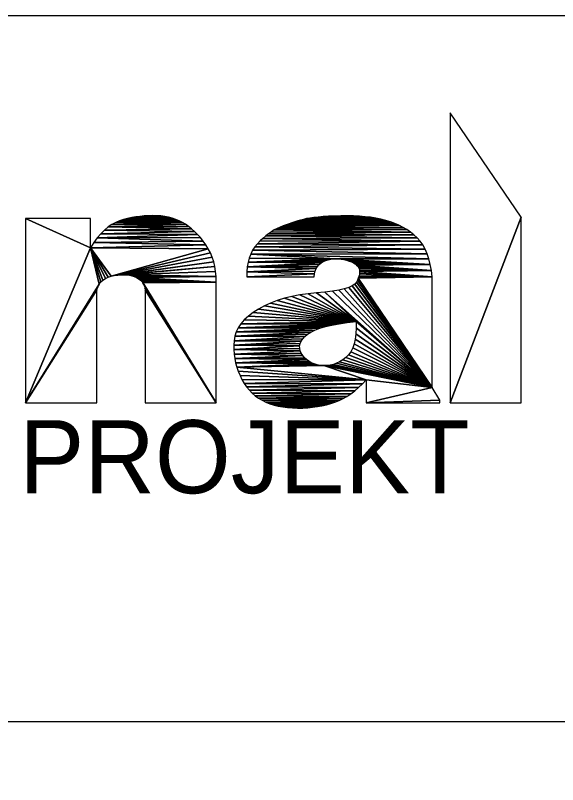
# Model space of a CAD drawing. Extents: x 1400 to 3500, y -1100 to 385.
# Drawn here: x 2698.5 to 2783.8, y -909.9 to -788.9 of the extents above; entities that cross this region are included whole.
import ezdxf

# ---------------------------------------------------------------- set-up
doc = ezdxf.new("R2010")
doc.units = 0
doc.layers.add('Vrstva 1', color=7, linetype='Continuous')

msp = doc.modelspace()

# ---------------------------------------------------------------- linework, layer by layer
for points in [[(2600, -788.87), (3425, -788.87), (3425, -1050), (2600, -1050)], [(2766.9, -804.21), (2766.9, -849.81), (2778.1, -820.61)], [(2710.3, -825.41), (2710.3, -820.81), (2700.1, -820.81)], [(2700.1, -820.81), (2700.1, -849.81), (2710.3, -825.41)], [(2714.29, -821.42), (2713.68, -821.74), (2724.78, -821.44)], [(2724.78, -821.44), (2713.68, -821.74), (2725.28, -821.73)], [(2724.27, -821.18), (2714.29, -821.42), (2724.78, -821.44)], [(2714.91, -821.18), (2714.29, -821.42), (2724.27, -821.18)], [(2715.54, -820.99), (2714.91, -821.18), (2724.27, -821.18)], [(2716.17, -820.82), (2715.54, -820.99), (2723.74, -820.96)], [(2723.74, -820.96), (2715.54, -820.99), (2724.27, -821.18)], [(2716.81, -820.68), (2716.17, -820.82), (2723.18, -820.77)], [(2723.18, -820.77), (2716.17, -820.82), (2723.74, -820.96)], [(2717.45, -820.57), (2716.81, -820.68), (2722.61, -820.62)], [(2722.61, -820.62), (2716.81, -820.68), (2723.18, -820.77)], [(2718.11, -820.48), (2717.45, -820.57), (2722.01, -820.5)], [(2722.01, -820.5), (2717.45, -820.57), (2722.61, -820.62)], [(2718.76, -820.41), (2718.11, -820.48), (2721.39, -820.42)], [(2721.39, -820.42), (2718.11, -820.48), (2722.01, -820.5)], [(2719.43, -820.37), (2718.76, -820.41), (2721.39, -820.42)], [(2720.1, -820.36), (2719.43, -820.37), (2720.76, -820.37)], [(2720.76, -820.37), (2719.43, -820.37), (2721.39, -820.42)], [(2742.47, -821.34), (2742.03, -821.49), (2758.21, -821.59)], [(2742.93, -821.2), (2742.47, -821.34), (2757.51, -821.33)], [(2757.51, -821.33), (2742.47, -821.34), (2758.21, -821.59)], [(2743.38, -821.07), (2742.93, -821.2), (2756.79, -821.11)], [(2756.79, -821.11), (2742.93, -821.2), (2757.51, -821.33)], [(2743.82, -820.95), (2743.38, -821.07), (2756.79, -821.11)], [(2744.3, -820.84), (2743.82, -820.95), (2756.03, -820.92)], [(2756.03, -820.92), (2743.82, -820.95), (2756.79, -821.11)], [(2744.85, -820.75), (2744.3, -820.84), (2755.24, -820.76)], [(2755.24, -820.76), (2744.3, -820.84), (2756.03, -820.92)], [(2745.47, -820.66), (2744.85, -820.75), (2755.24, -820.76)], [(2746.17, -820.59), (2745.47, -820.66), (2754.41, -820.63)], [(2754.41, -820.63), (2745.47, -820.66), (2755.24, -820.76)], [(2746.95, -820.52), (2746.17, -820.59), (2753.53, -820.53)], [(2753.53, -820.53), (2746.17, -820.59), (2754.41, -820.63)], [(2747.79, -820.47), (2746.95, -820.52), (2753.53, -820.53)], [(2748.71, -820.43), (2747.79, -820.47), (2752.63, -820.45)], [(2752.63, -820.45), (2747.79, -820.47), (2753.53, -820.53)], [(2749.7, -820.4), (2748.71, -820.43), (2751.7, -820.41)], [(2751.7, -820.41), (2748.71, -820.43), (2752.63, -820.45)], [(2750.72, -820.39), (2749.7, -820.4), (2751.7, -820.41)], [(2778.1, -820.61), (2766.9, -849.81), (2778.1, -849.81)], [(2712.51, -822.64), (2711.94, -823.21), (2726.7, -822.86)], [(2713.09, -822.15), (2712.51, -822.64), (2726.24, -822.44)], [(2726.24, -822.44), (2712.51, -822.64), (2726.7, -822.86)], [(2713.68, -821.74), (2713.09, -822.15), (2725.76, -822.07)], [(2725.76, -822.07), (2713.09, -822.15), (2726.24, -822.44)], [(2725.28, -821.73), (2713.68, -821.74), (2725.76, -822.07)], [(2739.25, -822.62), (2738.79, -822.9), (2760.67, -822.96)], [(2739.71, -822.38), (2739.25, -822.62), (2760.1, -822.57)], [(2760.1, -822.57), (2739.25, -822.62), (2760.67, -822.96)], [(2740.18, -822.17), (2739.71, -822.38), (2759.5, -822.21)], [(2759.5, -822.21), (2739.71, -822.38), (2760.1, -822.57)], [(2740.64, -821.99), (2740.18, -822.17), (2759.5, -822.21)], [(2741.11, -821.81), (2740.64, -821.99), (2758.87, -821.88)], [(2758.87, -821.88), (2740.64, -821.99), (2759.5, -822.21)], [(2741.57, -821.64), (2741.11, -821.81), (2758.87, -821.88)], [(2742.03, -821.49), (2741.57, -821.64), (2758.21, -821.59)], [(2758.21, -821.59), (2741.57, -821.64), (2758.87, -821.88)], [(2711.38, -823.86), (2710.84, -824.59), (2728.03, -824.36)], [(2711.94, -823.21), (2711.38, -823.86), (2727.16, -823.32)], [(2727.16, -823.32), (2711.38, -823.86), (2727.61, -823.82)], [(2727.61, -823.82), (2711.38, -823.86), (2728.03, -824.36)], [(2726.7, -822.86), (2711.94, -823.21), (2727.16, -823.32)], [(2737.89, -823.56), (2737.45, -823.94), (2761.71, -823.85)], [(2761.71, -823.85), (2737.45, -823.94), (2762.18, -824.37)], [(2738.34, -823.21), (2737.89, -823.56), (2761.2, -823.39)], [(2761.2, -823.39), (2737.89, -823.56), (2761.71, -823.85)], [(2738.79, -822.9), (2738.34, -823.21), (2760.67, -822.96)], [(2760.67, -822.96), (2738.34, -823.21), (2761.2, -823.39)], [(2710.84, -824.59), (2710.3, -825.41), (2728.46, -824.94)], [(2728.46, -824.94), (2710.3, -825.41), (2728.86, -825.56)], [(2728.03, -824.36), (2710.84, -824.59), (2728.46, -824.94)], [(2736.59, -824.8), (2736.18, -825.29), (2762.6, -824.96)], [(2762.6, -824.96), (2736.18, -825.29), (2762.97, -825.62)], [(2737.02, -824.35), (2736.59, -824.8), (2762.18, -824.37)], [(2762.18, -824.37), (2736.59, -824.8), (2762.6, -824.96)], [(2737.45, -823.94), (2737.02, -824.35), (2762.18, -824.37)], [(2710.3, -825.41), (2700.1, -849.81), (2711.69, -831.15)], [(2710.3, -825.41), (2713.55, -829.88), (2728.86, -825.56)], [(2710.3, -825.41), (2713.08, -830.03), (2713.55, -829.88)], [(2710.3, -825.41), (2712.66, -830.24), (2713.08, -830.03)], [(2710.3, -825.41), (2712.28, -830.49), (2712.66, -830.24)], [(2710.3, -825.41), (2711.97, -830.8), (2712.28, -830.49)], [(2710.3, -825.41), (2711.69, -831.15), (2711.97, -830.8)], [(2728.86, -825.56), (2713.55, -829.88), (2729.2, -826.21)], [(2729.2, -826.21), (2713.55, -829.88), (2714.07, -829.77)], [(2729.2, -826.21), (2714.07, -829.77), (2729.48, -826.89)], [(2735.84, -825.82), (2735.55, -826.4), (2763.28, -826.35)], [(2736.18, -825.29), (2735.84, -825.82), (2762.97, -825.62)], [(2762.97, -825.62), (2735.84, -825.82), (2763.28, -826.35)], [(2729.48, -826.89), (2714.07, -829.77), (2729.71, -827.61)], [(2735.31, -827.03), (2735.12, -827.7), (2748.95, -827.15)], [(2748.95, -827.15), (2735.12, -827.7), (2748.55, -827.17)], [(2748.55, -827.17), (2735.12, -827.7), (2748.14, -827.23)], [(2748.14, -827.23), (2735.12, -827.7), (2747.73, -827.32)], [(2747.73, -827.32), (2735.12, -827.7), (2747.33, -827.44)], [(2747.33, -827.44), (2735.12, -827.7), (2746.95, -827.6)], [(2735.55, -826.4), (2735.31, -827.03), (2748.95, -827.15)], [(2763.28, -826.35), (2735.55, -826.4), (2763.56, -827.16)], [(2735.55, -826.4), (2748.95, -827.15), (2763.56, -827.16)], [(2748.95, -827.15), (2749.37, -827.16), (2763.56, -827.16)], [(2749.37, -827.16), (2749.78, -827.2), (2763.56, -827.16)], [(2763.56, -827.16), (2749.78, -827.2), (2763.78, -828.04)], [(2749.78, -827.2), (2750.2, -827.27), (2763.78, -828.04)], [(2750.2, -827.27), (2750.62, -827.38), (2763.78, -828.04)], [(2750.62, -827.38), (2751.02, -827.51), (2763.78, -828.04)], [(2751.02, -827.51), (2751.38, -827.65), (2763.78, -828.04)], [(2729.71, -827.61), (2714.07, -829.77), (2714.6, -829.71)], [(2729.71, -827.61), (2714.6, -829.71), (2729.89, -828.36)], [(2729.89, -828.36), (2714.6, -829.71), (2715.1, -829.67)], [(2729.89, -828.36), (2715.1, -829.67), (2715.58, -829.67)], [(2729.89, -828.36), (2715.58, -829.67), (2730.01, -829.15)], [(2734.99, -828.43), (2734.92, -829.2), (2745.86, -828.7)], [(2745.86, -828.7), (2734.92, -829.2), (2745.7, -829.09)], [(2735.12, -827.7), (2734.99, -828.43), (2746.61, -827.81)], [(2746.61, -827.81), (2734.99, -828.43), (2746.32, -828.06)], [(2746.32, -828.06), (2734.99, -828.43), (2746.07, -828.36)], [(2746.07, -828.36), (2734.99, -828.43), (2745.86, -828.7)], [(2746.95, -827.6), (2735.12, -827.7), (2746.61, -827.81)], [(2751.38, -827.65), (2751.69, -827.8), (2763.78, -828.04)], [(2751.69, -827.8), (2751.96, -827.96), (2763.78, -828.04)], [(2751.96, -827.96), (2752.18, -828.13), (2763.78, -828.04)], [(2763.78, -828.04), (2752.18, -828.13), (2763.97, -828.99)], [(2752.18, -828.13), (2752.37, -828.31), (2763.97, -828.99)], [(2752.37, -828.31), (2752.51, -828.5), (2763.97, -828.99)], [(2752.51, -828.5), (2752.6, -828.7), (2763.97, -828.99)], [(2752.6, -828.7), (2752.66, -828.92), (2763.97, -828.99)], [(2730.01, -829.15), (2715.58, -829.67), (2730.08, -829.96)], [(2715.58, -829.67), (2716.03, -829.69), (2730.08, -829.96)], [(2716.03, -829.69), (2716.45, -829.75), (2730.08, -829.96)], [(2716.45, -829.75), (2716.85, -829.84), (2730.08, -829.96)], [(2716.85, -829.84), (2717.22, -829.96), (2730.08, -829.96)], [(2734.92, -829.2), (2734.9, -830.01), (2745.58, -829.53)], [(2745.58, -829.53), (2734.9, -830.01), (2745.5, -830.01)], [(2745.7, -829.09), (2734.92, -829.2), (2745.58, -829.53)], [(2752.57, -829.92), (2752.47, -830.2), (2764.1, -830.01)], [(2752.64, -829.65), (2752.57, -829.92), (2764.1, -830.01)], [(2752.68, -829.39), (2752.64, -829.65), (2764.1, -830.01)], [(2752.66, -828.92), (2752.68, -829.15), (2763.97, -828.99)], [(2763.97, -828.99), (2752.68, -829.15), (2764.1, -830.01)], [(2752.68, -829.15), (2752.68, -829.39), (2764.1, -830.01)], [(2717.22, -829.96), (2717.57, -830.11), (2730.08, -829.96)], [(2730.08, -829.96), (2717.57, -830.11), (2730.1, -830.81)], [(2717.57, -830.11), (2717.88, -830.28), (2730.1, -830.81)], [(2717.88, -830.28), (2718.15, -830.47), (2730.1, -830.81)], [(2718.15, -830.47), (2718.38, -830.68), (2730.1, -830.81)], [(2718.38, -830.68), (2718.57, -830.91), (2730.1, -830.81)], [(2730.1, -830.81), (2718.57, -830.91), (2730.1, -849.81)], [(2718.57, -830.91), (2718.71, -831.16), (2730.1, -849.81)], [(2751.93, -831.12), (2751.52, -831.4), (2764.1, -847.41)], [(2752.18, -830.81), (2751.93, -831.12), (2764.1, -847.41)], [(2752.34, -830.5), (2752.18, -830.81), (2764.1, -847.41)], [(2752.47, -830.2), (2752.34, -830.5), (2764.1, -847.41)], [(2764.1, -830.01), (2752.47, -830.2), (2764.1, -847.41)], [(2711.69, -831.15), (2700.1, -849.81), (2711.47, -831.56)], [(2711.47, -831.56), (2700.1, -849.81), (2711.3, -832.01)], [(2711.3, -832.01), (2700.1, -849.81), (2711.3, -849.81)], [(2718.71, -831.16), (2718.82, -831.42), (2730.1, -849.81)], [(2718.82, -831.42), (2718.88, -831.71), (2730.1, -849.81)], [(2718.88, -831.71), (2718.9, -832.01), (2730.1, -849.81)], [(2718.9, -832.01), (2718.9, -849.81), (2730.1, -849.81)], [(2748.39, -832.25), (2747.22, -832.4), (2764.1, -847.41)], [(2749.39, -832.08), (2748.39, -832.25), (2764.1, -847.41)], [(2750.26, -831.88), (2749.39, -832.08), (2764.1, -847.41)], [(2750.97, -831.65), (2750.26, -831.88), (2764.1, -847.41)], [(2751.52, -831.4), (2750.97, -831.65), (2764.1, -847.41)], [(2740.84, -833.37), (2739.72, -833.72), (2752.12, -837.03)], [(2742.01, -833.08), (2740.84, -833.37), (2752.12, -837.03)], [(2743.25, -832.84), (2742.01, -833.08), (2752.12, -837.03)], [(2744.55, -832.66), (2743.25, -832.84), (2752.12, -837.03)], [(2745.91, -832.52), (2744.55, -832.66), (2752.12, -837.03)], [(2747.22, -832.4), (2745.91, -832.52), (2752.12, -837.03)], [(2747.22, -832.4), (2752.12, -837.03), (2764.1, -847.41)], [(2737.68, -834.57), (2736.75, -835.07), (2752.12, -837.03)], [(2738.67, -834.12), (2737.68, -834.57), (2752.12, -837.03)], [(2739.72, -833.72), (2738.67, -834.12), (2752.12, -837.03)], [(2735.91, -835.61), (2735.16, -836.17), (2752.12, -837.03)], [(2736.75, -835.07), (2735.91, -835.61), (2752.12, -837.03)], [(2734.53, -836.76), (2733.99, -837.37), (2752.12, -837.03)], [(2752.12, -837.03), (2733.99, -837.37), (2750.72, -837.19)], [(2750.72, -837.19), (2733.99, -837.37), (2749.45, -837.37)], [(2735.16, -836.17), (2734.53, -836.76), (2752.12, -837.03)], [(2752.12, -837.03), (2752.14, -838.03), (2764.1, -847.41)], [(2733.57, -838), (2733.24, -838.65), (2746.39, -838.08)], [(2746.39, -838.08), (2733.24, -838.65), (2745.62, -838.37)], [(2745.62, -838.37), (2733.24, -838.65), (2744.97, -838.68)], [(2749.45, -837.37), (2733.57, -838), (2748.3, -837.58)], [(2733.99, -837.37), (2733.57, -838), (2749.45, -837.37)], [(2748.3, -837.58), (2733.57, -838), (2747.28, -837.82)], [(2747.28, -837.82), (2733.57, -838), (2746.39, -838.08)], [(2752.14, -838.03), (2752.1, -838.94), (2764.1, -847.41)], [(2733.02, -839.33), (2732.91, -840.03), (2744.05, -839.38)], [(2744.05, -839.38), (2732.91, -840.03), (2743.72, -839.74)], [(2733.24, -838.65), (2733.02, -839.33), (2744.97, -838.68)], [(2744.97, -838.68), (2733.02, -839.33), (2744.46, -839.02)], [(2744.46, -839.02), (2733.02, -839.33), (2744.05, -839.38)], [(2752.1, -838.94), (2751.99, -839.77), (2764.1, -847.41)], [(2732.91, -840.03), (2732.87, -840.73), (2743.47, -840.11)], [(2743.47, -840.11), (2732.87, -840.73), (2743.31, -840.48)], [(2743.31, -840.48), (2732.87, -840.73), (2743.23, -840.86)], [(2732.87, -840.73), (2732.87, -841.43), (2743.23, -840.86)], [(2743.72, -839.74), (2732.91, -840.03), (2743.47, -840.11)], [(2751.82, -840.51), (2751.58, -841.18), (2764.1, -847.41)], [(2751.99, -839.77), (2751.82, -840.51), (2764.1, -847.41)], [(2743.23, -840.86), (2732.87, -841.43), (2743.24, -841.24)], [(2743.24, -841.24), (2732.87, -841.43), (2743.33, -841.62)], [(2732.87, -841.43), (2732.92, -842.13), (2743.33, -841.62)], [(2743.33, -841.62), (2732.92, -842.13), (2743.49, -842.01)], [(2743.49, -842.01), (2732.92, -842.13), (2743.73, -842.38)], [(2751.28, -841.77), (2750.91, -842.28), (2764.1, -847.41)], [(2751.58, -841.18), (2751.28, -841.77), (2764.1, -847.41)], [(2732.92, -842.13), (2733.01, -842.82), (2743.73, -842.38)], [(2743.73, -842.38), (2733.01, -842.82), (2744.01, -842.72)], [(2744.01, -842.72), (2733.01, -842.82), (2744.32, -843.01)], [(2733.01, -842.82), (2733.16, -843.5), (2744.32, -843.01)], [(2744.32, -843.01), (2733.16, -843.5), (2744.68, -843.27)], [(2750.01, -843.06), (2749.53, -843.36), (2764.1, -847.41)], [(2750.48, -842.7), (2750.01, -843.06), (2764.1, -847.41)], [(2750.91, -842.28), (2750.48, -842.7), (2764.1, -847.41)], [(2744.68, -843.27), (2733.16, -843.5), (2745.07, -843.49)], [(2745.07, -843.49), (2733.16, -843.5), (2745.5, -843.67)], [(2733.16, -843.5), (2733.34, -844.18), (2745.5, -843.67)], [(2745.5, -843.67), (2733.34, -844.18), (2745.97, -843.81)], [(2745.97, -843.81), (2733.34, -844.18), (2746.49, -843.91)], [(2746.49, -843.91), (2733.34, -844.18), (2747.02, -843.96)], [(2747.02, -843.96), (2733.34, -844.18), (2753.7, -846.21)], [(2733.34, -844.18), (2733.57, -844.85), (2753.7, -846.21)], [(2747.02, -843.96), (2753.7, -846.21), (2764.1, -847.41)], [(2747.54, -843.96), (2747.02, -843.96), (2764.1, -847.41)], [(2748.05, -843.9), (2747.54, -843.96), (2764.1, -847.41)], [(2748.55, -843.77), (2748.05, -843.9), (2764.1, -847.41)], [(2749.05, -843.59), (2748.55, -843.77), (2764.1, -847.41)], [(2749.53, -843.36), (2749.05, -843.59), (2764.1, -847.41)], [(2733.57, -844.85), (2733.85, -845.52), (2753.7, -846.21)], [(2733.85, -845.52), (2734.16, -846.16), (2753.7, -846.21)], [(2734.16, -846.16), (2734.51, -846.75), (2753.7, -846.21)], [(2753.7, -846.21), (2734.51, -846.75), (2753.11, -846.83)], [(2734.51, -846.75), (2734.89, -847.31), (2753.11, -846.83)], [(2753.11, -846.83), (2734.89, -847.31), (2752.52, -847.4)], [(2753.7, -846.21), (2753.7, -849.81), (2764.1, -847.41)], [(2734.89, -847.31), (2735.32, -847.81), (2752.52, -847.4)], [(2752.52, -847.4), (2735.32, -847.81), (2751.91, -847.91)], [(2735.32, -847.81), (2735.76, -848.28), (2751.91, -847.91)], [(2751.91, -847.91), (2735.76, -848.28), (2751.3, -848.38)], [(2764.1, -847.41), (2753.7, -849.81), (2765.3, -849.41)], [(2735.76, -848.28), (2736.26, -848.7), (2751.3, -848.38)], [(2751.3, -848.38), (2736.26, -848.7), (2750.68, -848.79)], [(2736.26, -848.7), (2736.78, -849.07), (2750.68, -848.79)], [(2750.68, -848.79), (2736.78, -849.07), (2750.06, -849.15)], [(2736.78, -849.07), (2737.34, -849.4), (2750.06, -849.15)], [(2750.06, -849.15), (2737.34, -849.4), (2749.43, -849.46)], [(2737.34, -849.4), (2737.93, -849.69), (2749.43, -849.46)], [(2749.43, -849.46), (2737.93, -849.69), (2748.78, -849.71)], [(2737.93, -849.69), (2738.55, -849.94), (2748.78, -849.71)], [(2748.78, -849.71), (2738.55, -849.94), (2748.12, -849.93)], [(2748.12, -849.93), (2738.55, -849.94), (2747.45, -850.12)], [(2738.55, -849.94), (2739.2, -850.15), (2747.45, -850.12)], [(2747.45, -850.12), (2739.2, -850.15), (2746.74, -850.27)], [(2739.2, -850.15), (2739.88, -850.32), (2746.74, -850.27)], [(2746.74, -850.27), (2739.88, -850.32), (2746.02, -850.4)], [(2739.88, -850.32), (2740.59, -850.46), (2746.02, -850.4)], [(2746.02, -850.4), (2740.59, -850.46), (2745.28, -850.5)], [(2740.59, -850.46), (2741.34, -850.56), (2745.28, -850.5)], [(2765.3, -849.41), (2753.7, -849.81), (2765.3, -849.81)], [(2745.28, -850.5), (2741.34, -850.56), (2744.51, -850.57)], [(2741.34, -850.56), (2742.11, -850.61), (2744.51, -850.57)], [(2744.51, -850.57), (2742.11, -850.61), (2743.72, -850.62)], [(2742.11, -850.61), (2742.91, -850.63), (2743.72, -850.62)]]:
    msp.add_lwpolyline(points, close=True)
at = {"layer": 'Vrstva 1'}
msp.add_line((3175.6, -900), (2600, -900), dxfattribs=at)

# ---------------------------------------------------------------- texts
msp.add_text('PROJEKT', height=11.495).set_placement((2699.1, -864.03))

doc.saveas('drawing.dxf')
